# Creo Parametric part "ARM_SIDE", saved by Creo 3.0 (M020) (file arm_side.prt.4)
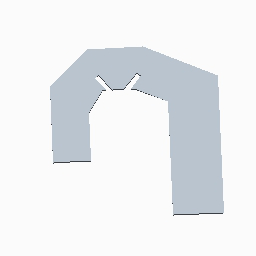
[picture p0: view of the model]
Units: millimeter Newton Second (mmNs); MM, TONNE, SECS

Created from: MMNS_PART_SOLID.PRT

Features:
  1. datum plane "RIGHT"
  2. datum plane "TOP"
  3. datum plane "FRONT"
  4. coordinate system
  5. sketch "Sketch 1"
  6. extrusion "Extrude 1"
  7. sketch "Sketch 2"
  8. sketch "Sketch 3"
  9. extruded cut "Extrude 3"
  10. sketch "Sketch 4"
  11. extruded cut "Extrude 4"

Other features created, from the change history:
  datum plane "DTM1"
  sketch "Sketch 2"
  extruded cut "Extrude 2"
  extruded cut "Extrude 3"

Surfaces: 24 plane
